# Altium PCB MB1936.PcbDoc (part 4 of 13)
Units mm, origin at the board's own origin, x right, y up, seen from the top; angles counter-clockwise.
Board outline 172 x 137 mm, 6 copper layers (Top Layer, Signal Layer 1, Signal Layer 2, Signal Layer 3, Signal Layer 4, Bottom Layer), stack 1.549 mm thick; 859 components, 672 nets, 3477 pads, 2222 vias.
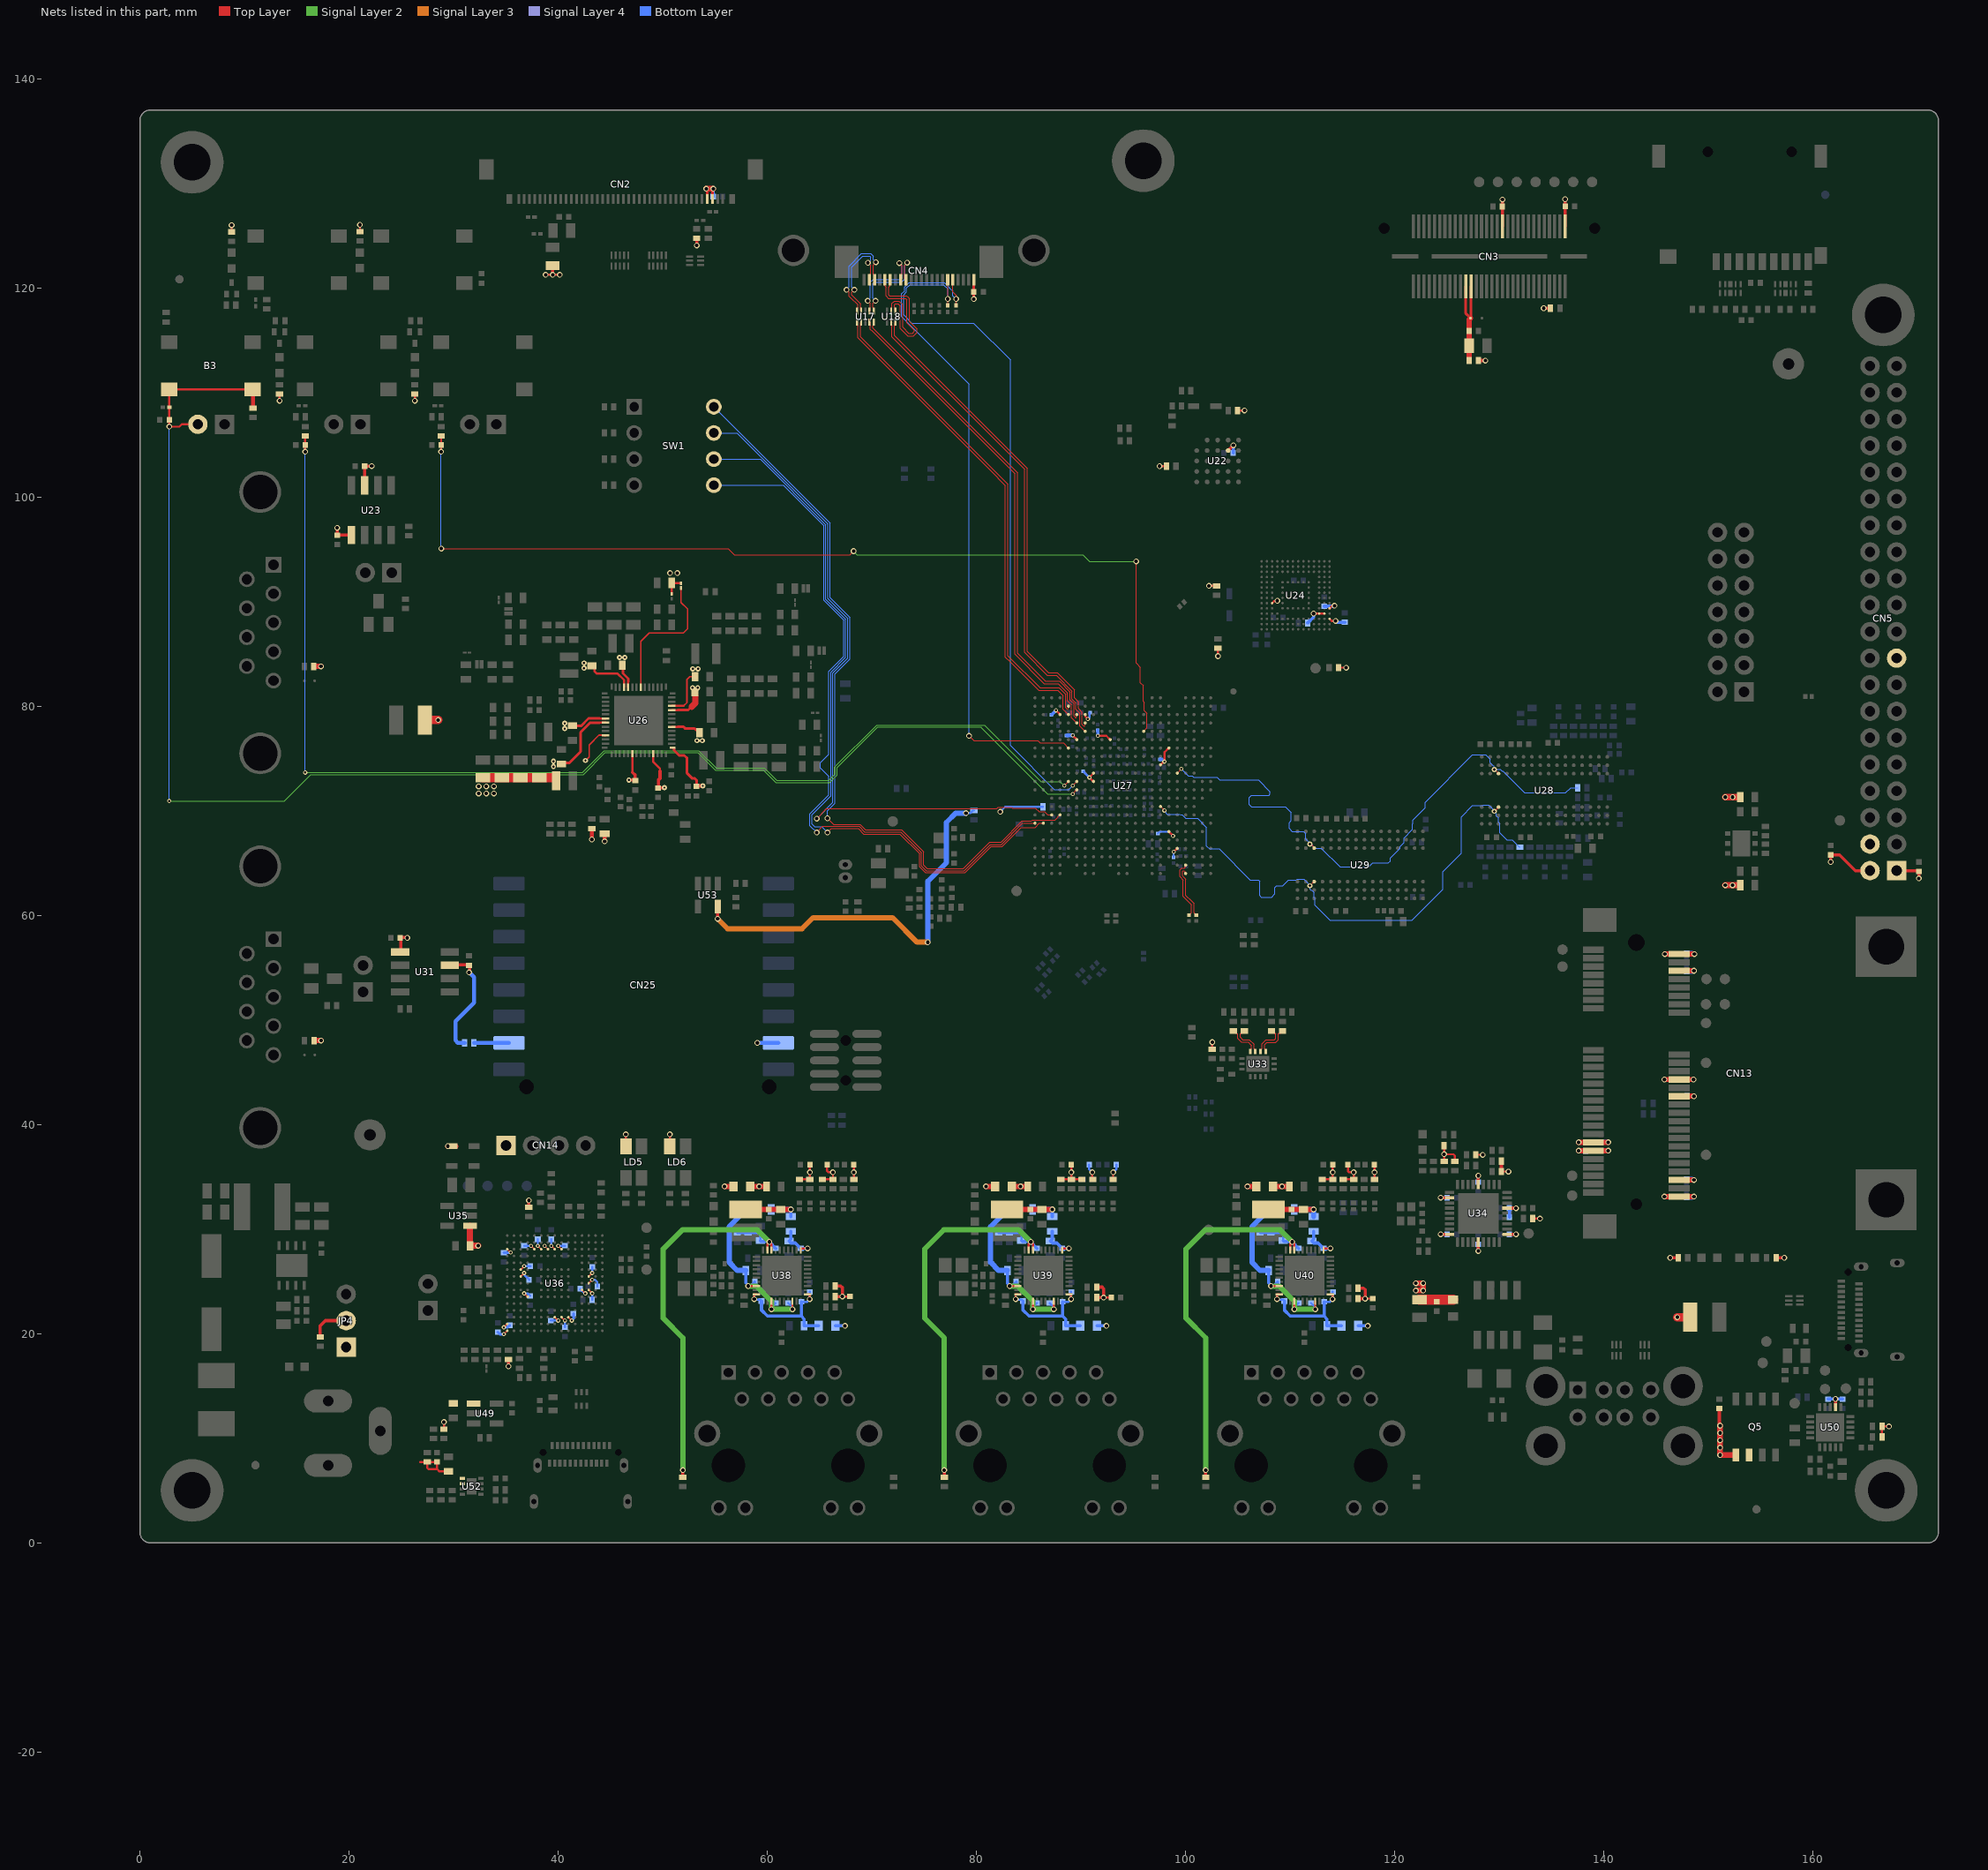
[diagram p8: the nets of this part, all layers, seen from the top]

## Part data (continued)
R93 R182 R183 R184 R188 R189 R190 R289: library part MCD-00052, "Resistor,0R,0402,5%,1/16W", Manufacturer=YAGEO, Manufacturer_Part_Number=RC0402JR-070RL, Package=0402
R94 R135 R136 R137 R138 R139 R140 R141 R142 R143 R144 R145 R146 R147 R148 R149 R150 R151 R152 R161 R162 R163 R164 R165 R166 R167 R168 R169 R173 R174 R175 R176 R177 R178 R179 R180 R185 R186 R187 R196 R197 R198 R247: library part MCD-02978, "Resistor, 22R, 0201, +/-1%, 1/20W", Manufacturer=YAGEO, Manufacturer_Part_Number=RC0201FR-0722RL, Package=0201
R95 R97 R98 R99 R100 R102 R105 R217 R218 R227 R229 R239: library part MCD-00059, "Resistor, 100K, 0402, +/-1%, 1/16W", Manufacturer=YAGEO, Manufacturer_Part_Number=RC0402FR-07100KL, Package=0402
R108 R109 R110 R111 R112 R113 R114 R115 R116 R117 R118 R119 R120 R121 R122 R123 R124 R292 R293 R294 R295 R296 R297 R298 R299 R300 R301 R302 R303 R304 R305 R306 R307: library part MCD-00065, "Resistor,4K7,0402,1%,1/16W", Alternate_Manufacturer=YAGEO, Alternate_Manufacturer_Part_Number=RT0402FRE074K7L, Manufacturer_Part_Number=RC0402FR-074K7L, Package=R0402
R130 R132: library part MCD-00062, "Resistor, 330R, 0402, +/-1%, 1/16W", Manufacturer=YAGEO, Manufacturer_Part_Number=RC0402FR-07330RL, Package=0402
R131 R133: library part MCD-02665, "Resistor, 1K, 0402, +/-0.1%, 1/16W, +/-25ppm/°C", Manufacturer=YAGEO, Manufacturer_Part_Number=RT0402BRD071KL, Package=0402
R134 R153 R207 R209: library part MCD-00455, "Resistor, 33R, 0402, +/-1%, 1/16W", Manufacturer=YAGEO, Manufacturer_Part_Number=RC0402FR-0733RL, Package=0402
R158 R159 R160 R315 R317 R319 R320 R321 R322: library part MCD-00065, "Resistor,4K7,0402,1%,1/16W", Alternate_Manufacturer=YAGEO, Alternate_Manufacturer_Part_Number=RT0402FRE074K7L, Manufacturer_Part_Number=RC0402FR-074K7L, Package=0402
R170: library part MCD-00187, "Resistor, 12K, 0402, +/-1%, 1/16W", Manufacturer=YAGEO, Manufacturer_Part_Number=RC0402FR-0712KL, Package=0402
R191 R192 R193 R195 R202 R203 R260 R261 R314 R316 R318: library part MCD-00068, "Resistor,1K5,0402,1%,1/16W", Manufacturer=YAGEO, Manufacturer_Part_Number=RC0402FR-071K5L, Package=0402
R194: library part MCD-00185, "Resistor, 3K, 0402, +/-1%, 1/16W", Manufacturer=YAGEO, Manufacturer_Part_Number=RC0402FR-073KL, Package=0402
R199 R200 R201: library part MCD-00183, "Resistor,2K49,0402,1%,1/16W", Manufacturer=YAGEO, Manufacturer_Part_Number=RC0402FR-072K49L, Package=0402
R204: library part MCD-00421, "Resistor,20K,0402,1%,1/16W", Alternate_Manufacturer=N/A, Manufacturer=YAGEO, Manufacturer_Part_Number=RC0402FR-0720KL, Package=0402
R208: library part MCD-00367, "Resistor,110K,0402,1%,1/16W", Alternate_Manufacturer=N/A, Manufacturer=YAGEO, Manufacturer_Part_Number=RC0402FR-07110KL, Package=0402
R216 R221 R222: library part MCD-00333, "Resistor, 5K1, 0402, +/-1%, 1/16W", Manufacturer=YAGEO, Manufacturer_Part_Number=RC0402FR-075K1L, Package=0402
R219: library part MCD-02335, "Resistor, 140K, 0402, +/-1%, 1/16W", Manufacturer=YAGEO, Manufacturer_Part_Number=RC0402FR-07140KL, Package=0402
R225: library part MCD-02232, "Resistor, 22mR, 0603, +/-1%, 1/3W", Manufacturer=PANASONIC, Manufacturer_Part_Number=ERJ-3BWFR022V, Package=0603
R231: library part MCD-00435, "Resistor, 24K, 0402, +/-1%, 1/16W", Manufacturer=YAGEO, Manufacturer_Part_Number=RC0402FR-0724KL, Package=0402
R232 R327: library part MCD-02265, "Resistor,100K,0402,0.5%,1/16W", Manufacturer=YAGEO, Manufacturer_Part_Number=RC0402DR-07100KL, Package=0402
R233 R234 R235 R236 R237 R238: library part MCD-00064, "Resistor,510R,0402,1%,1/16W", Manufacturer=YAGEO, Manufacturer_Part_Number=RC0402FR-07510RL, Package=0402
R240: library part MCD-00381, "Resistor, 1K3, 0402, +/-1%, 1/16W", Manufacturer=YAGEO, Manufacturer_Part_Number=RC0402FR-071K3L, Package=0402
R241: library part MCD-00409, "Resistor, 1K8, 0402, +/-1%, 1/16W", Manufacturer=YAGEO, Manufacturer_Part_Number=RC0402FR-071K8L, Package=0402
R242: library part MCD-02455, "Resistor, 3K9, 0402, +/-1%, 1/16W, +/-100ppm/°C", Manufacturer=YAGEO, Manufacturer_Part_Number=RC0402FR-073K9L, Package=0402
R243: library part MCD-00483, "Resistor, 470K, 0402, +/-1%, 1/16W", Manufacturer=YAGEO, Manufacturer_Part_Number=RC0402FR-07470KL, Package=0402
R244: library part MCD-00495, "Resistor, 560K, 0402, +/-1%, 1/16W", Manufacturer=YAGEO, Manufacturer_Part_Number=RC0402FR-07560KL, Package=0402
R249: library part MCD-00056, "Resistor, 0R, 0603, +/-5%, 1/10W", Manufacturer=YAGEO, Manufacturer_Part_Number=RC0603JR-070RL, Package=0603
R250 R251 R274 R285 R287: library part MCD-00417, "Resistor, 200R, 0402, +/-1%, 1/16W", Manufacturer=YAGEO, Manufacturer_Part_Number=RC0402FR-07200RL, Package=0402
R253 R254 R255 R256 R257 R258 R259 R263 R264 R265 R266 R268 R271 R273 R275 R276 R277 R278 R279 R280 R281 R282 R283 R284: library part MCD-00054, "Resistor, 56R, 0402, +/-1%, 1/16W", Alternate_Manufacturer=N/A, Manufacturer=YAGEO, Manufacturer_Part_Number=RC0402FR-0756RL, Package=0402
R270: library part MCD-01819, "Resistor,100R,0402,0,5%,1/16W,±100ppm/°C", Alternate_Manufacturer=N/A, Manufacturer=YAGEO, Manufacturer_Part_Number=RC0402DR-07100RL, Package=0402
R308 R309 R310 R311 R312 R313: library part MCD-00056, "Resistor,0R,0603,5%,1/10W", Manufacturer=YAGEO, Manufacturer_Part_Number=RC0603JR-070RL, Package=0603
R325: library part MCD-00182, "Resistor, 1M, 0402, +/-1%, 1/16W", Manufacturer=YAGEO, Manufacturer_Part_Number=RC0402FR-071ML, Package=0402
SB1: library part MCD-00071, "Solder Bridge ON", Manufacturer=YAGEO, Manufacturer_Part_Number=RC0603JR-070RL, Package=SB0603
SB2 SB3: library part MCD-01618, "Solder Bridge 0402 ON", Manufacturer=YAGEO, Manufacturer_Part_Number=RC0402JR-070RL, Package=SB0402
SW1: library part MCD-02256, "Quad SPST switch, TH, 2.54mm pitch, height 7.5mm", Alternate_Manufacturer="TE Connectivity", Alternate_Manufacturer_Part_Number=5435640-2, Manufacturer=GRAYHILL, Package="DIP8 2.54mm pitch"
TP1 TP2 TP3 TP4 TP5 TP6 TP7 TP34 TP36 TP37 TP38 TP39: library part MCD-00074, "Test Point 1mm", Manufacturer=N/A, Manufacturer_Part_Number=n/a
TP8 TP22: library part MCD-00713, "Vero Technologies 1.02mm Black Terminal Post", Manufacturer=VERO, Manufacturer_Part_Number=20-2137
TP9 TP11 TP12 TP13 TP14 TP15 TP16 TP17 TP18 TP19 TP20 TP21 TP23 TP24 TP25 TP26 TP27 TP28 TP29 TP30 TP31 TP32 TP35: library part MCD-00074, "Test Point 1mm", Manufacturer=n/a
TP10: library part MCD-00631, "Test Point 0.6mm", Manufacturer=N/A
TP33: library part MCD-00074, "Test Point 1mm", Manufacturer=N/A
U1 U2 U3 U4 U10 U11 U12 U13 U14 U15 U16 U19 U20 U21: library part MCD-00170, "ESD protection 6V1", Manufacturer=STMICROELECTRONICS, Manufacturer_HQ_COO=EU, Manufacturer_Part_Number=ESDALC6V1-1U2
U5 U6 U17: library part MCD-03059, "ESD protection & Common Filter High Speed serial Interfaces , 0.4 pitch", Manufacturer=STMICROELECTRONICS, Package=uQFN-10L
U7 U18 U42 U45 U46: library part MCD-03060, "ESD protection & Common Filter High Speed serial Interfaces , 0.4 pitch", Manufacturer=STMICROELECTRONICS, Package=uQFN-6
U8 U9: library part MCD-00667, "4-line ESD protection for high speed lines", Manufacturer=STMICROELECTRONICS, Manufacturer_HQ_COO=EU, Package=uQFN-10L
U22: library part MCD-00114, "Memory,Serial-NOR,512Mb,3V", Manufacturer=MACRONIX
U23 U31: library part MCD-00129, "High-Speed CAN Flexible Data Rate Transceiver", Manufacturer=MICROCHIP, Manufacturer_Part_Number=MCP2562FDT-H/SN
U24: library part MCD-02799, "Memory, eMMC, 4GB, 15nm ,WFBGA , 153 pins", Manufacturer=KIOXIA, Manufacturer_Part_Number=THGBMTG5D1LBAIL, Package=WFBGA153
U25 U32: library part MCD-00143, "Automotive dual-line Transil. ESD CAN", Manufacturer=STMICROELECTRONICS, Manufacturer_HQ_COO=EU, Manufacturer_Part_Number=ESDCAN24-2BLY
U26: library part MCD-03000, Manufacturer=STMICROELECTRONICS, Manufacturer_Part_Number=STPMIC25A, Package=VQFN
U27: library part MCD-02000, "MPU, ARM Cortex-A35 + M33 32-bit MPU, 808KB RAM, With Crypto", Manufacturer=STMICROELECTRONICS, Manufacturer_HQ_COO=EU, Package=LFBGA-436
U28 U29: library part MCD-03523, "Memory, DDR4 SDRAM, 1V2, 16Gbit, FBGA96", Manufacturer=MICRON, Package=FBGA-96
U30: library part MCD-00581, "LDO Linear Voltage Regulator IC Positive Adjustable 1 Output Adjustable 1.3A 6-DFN (3x3)", Manufacturer=STMICROELECTRONICS, Manufacturer_HQ_COO=EU, Package="DFN6 (3x3)"
U33: library part MCD-02349, "Crystal-less Two Output PCIe Gen1/2/3 Clock Generator 100Mhz , 2.25V to 3.6V, 100ppm", Manufacturer=MICROCHIP, Package="14 QFN"
U34: library part MCD-00145, "USB HUB 2,0 Controller", Manufacturer=MICROCHIP
U35: library part MCD-02514, "LDO, 3.3V, 300mA, High input voltage: 2.5V to 28V, SOT23-5L", Manufacturer=STMICROELECTRONICS, Package=SOT23-5L
U36: library part MCD-02706, "MCU, Arm Cortex-M7 32-bit MCU, 512KB Flash, 276KB RAM, With Crypto", Manufacturer=STMICROELECTRONICS, Manufacturer_Part_Number=STM32F723IEK6, Package=BGA176
U37: library part MCD-02219, "3 A DC step-down switching regulator", Manufacturer=STMICROELECTRONICS, Manufacturer_HQ_COO=EU, Package=VFQFPN
U38 U39 U40: library part MCD-01130, "10/100/1000M GIGABIT Ethernet Transceiver, QFN40 , SMPS version", Manufacturer=REALTEK
U41: library part MCD-00123, "IC,Dual-Channel-Power-Switch,500mA,100mR,SO8", Manufacturer=STMICROELECTRONICS, Manufacturer_HQ_COO=EU
U43 U48: library part MCD-01207, "High power Transient voltage suppressor:25V/35A EOS and ESD transients protection.", Manufacturer=STMICROELECTRONICS, Manufacturer_HQ_COO=EU, Manufacturer_Part_Number=ESDA25P35-1U1M, Package=QFN1610
U44 U51: library part MCD-01026, "High power transient voltage suppressor", Manufacturer=STMICROELECTRONICS, Manufacturer_HQ_COO=EU, Manufacturer_Part_Number=ESDA7P120-1U1M, Package=QFN1610
U47: library part MCD-00649, "Common mode filter with ESD protection for USB 2.0 interface", Manufacturer=STMICROELECTRONICS, Manufacturer_HQ_COO=EU, Manufacturer_Part_Number=ECMF02-2AMX6
U49: library part MCD-00159, "500mA, Enhanced single channel power switches with active high enable pin", Alternate_Manufacturer="TEXAS INSTRUMENTS", Alternate_Manufacturer_Part_Number=TPS2051C, Manufacturer=STMICROELECTRONICS, Manufacturer_HQ_COO=EU
U50: library part MCD-02130, "USB Type-C Port Protection for USB DRP Power Delivery, PPS compliant", Manufacturer=STMICROELECTRONICS, Manufacturer_HQ_COO=EU, Package=QFN-20L
U52: library part MCD-02532, "IC, eFuse with Fast Overvoltage Protection 2.7V to 18V 4A 34mOhm 8-Pin WSON", Manufacturer="TEXAS INSTRUMENTS", Package=WSON8
U53: library part MCD-02043, "Single,  rail to rail input/ouput 880Khz operational amplifiers", Manufacturer=STMICROELECTRONICS, Manufacturer_HQ_COO=EU, Package=SOT23-5
X1: library part MCD-01479, "Crystal, 32.768kHz, 6pF, +/-20ppm, 80K, 2.05x1.2mm", Manufacturer=NDK, Manufacturer_Part_Number=NX2012SA-32.768KHZ-EXS00A-MU00527, Package=2.05x1.2mm
X2: library part MCD-02343, "Oscillator, SPXO, 40Mhz, +/-50ppm, 1.8V, square wave, 1.6x1.2mm", Alternate_Manufacturer=N/A, Manufacturer=NDK, Manufacturer_Part_Number="NZ1612SH 40MHZ END5951A", Package=1.6x1.2mm
X3 X7: library part MCD-01036, "Crystal, 24MHz, 6pF, +/-20ppm, 80R, 2x1.6mm", Manufacturer=NDK, Manufacturer_Part_Number=NX2016SA-24MHZ-EXS00A-CS10820, Package=2x1.6mm
X4 X5 X6: library part MCD-01463, "Crystal 25Mhz, 10pF, -+50PPM, SMD", Manufacturer=NDK, Manufacturer_Part_Number=NX3225GA-25MHZ-EXS00A-CG06750, Package=3.2x2.5mm

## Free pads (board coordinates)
  round 3 hole 2.2 paste-2539.97 mask+0.05: 1(62.5,123.578) 1(85.5,123.578)
  round 6 hole 3.5: 1(166.725,117.4) 7(95.954,132.163)
  round 6 hole 3.5 mask+0.05: 5(5,5) 5(5,132) 5(167,5)

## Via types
v1: diameter 0.55, hole 0.35, Top Layer to Bottom Layer, 1661 vias
v2: diameter 0.4, hole 0.2, Top Layer to Bottom Layer, tented both sides, 253 vias
v3: diameter 0.5, hole 0.2, Top Layer to Bottom Layer, 157 vias
v4: diameter 0.5, hole 0.25, Top Layer to Bottom Layer, 145 vias
v5: diameter 0.4, hole 0.2, Top Layer to Bottom Layer, 6 vias

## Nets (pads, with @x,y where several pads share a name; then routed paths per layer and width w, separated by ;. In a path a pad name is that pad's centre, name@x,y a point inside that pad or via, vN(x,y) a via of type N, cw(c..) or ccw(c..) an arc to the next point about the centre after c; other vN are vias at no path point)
1V0_AVDD_RGMII1: C301.2 C305.2 C320.2 C321.2 R309.1 U39.3 U39.8 U39.38 | length 20.5
  Top Layer w0.2: v1(83.175,24.55) U39.38@83.95,24.55 ; v1(85.4,22.325) U39.3@85.4,23.1 ; v1(87.4,22.325) U39.8@87.4,23.1
  Signal Layer 2 w0.5: v1(83.175,24.55) 83.95,24.55 85.4,23.1 v1(85.4,22.325) v1(87.4,22.325)
  Bottom Layer w0.2: v1(85.4,22.325) 85.4,22.525 C321.2@85.8,22.925 ; C320.2@87,22.925 87.4,22.525 v1(87.4,22.325)
  Bottom Layer w0.3: C301.2@82.931,26.044 C301.2@82.95,26.025 82.95,24.843 83.175,24.618 v1(83.175,24.55) 83.223,24.598 83.448,24.598 83.67,24.82 83.695,24.82 83.8,24.925 C305.2@83.8,24.95
  Bottom Layer w0.5: C301.2@82.931,26.044 82.125,26.044 81.35,26.819 81.35,30.225 83,31.875 R309.1@83.975,31.875
1V0_AVDD_RGMII2: C302.2 C306.2 C322.2 C323.2 R310.1 U38.3 U38.8 U38.38 | length 20.5
  Top Layer w0.2: v1(58.175,24.55) U38.38@58.95,24.55 ; v1(60.4,22.325) U38.3@60.4,23.1 ; v1(62.4,22.325) U38.8@62.4,23.1
  Signal Layer 2 w0.5: v1(58.175,24.55) 58.95,24.55 60.4,23.1 v1(60.4,22.325) v1(62.4,22.325)
  Bottom Layer w0.2: v1(60.4,22.325) 60.4,22.525 C323.2@60.8,22.925 ; C322.2@62,22.925 62.4,22.525 v1(62.4,22.325)
  Bottom Layer w0.3: C302.2@57.931,26.044 C302.2@57.95,26.025 57.95,24.843 58.175,24.618 v1(58.175,24.55) 58.223,24.598 58.448,24.598 58.67,24.82 58.695,24.82 58.8,24.925 C306.2@58.8,24.95
  Bottom Layer w0.5: C302.2@57.931,26.044 57.125,26.044 56.35,26.819 56.35,30.225 58,31.875 R310.1@58.975,31.875
1V0_AVDD_RGMII3: C300.2 C304.2 C318.2 C319.2 R308.1 U40.3 U40.8 U40.38 | length 20.5
  Top Layer w0.2: v1(108.175,24.55) U40.38@108.95,24.55 ; v1(110.4,22.325) U40.3@110.4,23.1 ; v1(112.4,22.325) U40.8@112.4,23.1
  Signal Layer 2 w0.5: v1(108.175,24.55) 108.95,24.55 110.4,23.1 v1(110.4,22.325) v1(112.4,22.325)
  Bottom Layer w0.2: v1(110.4,22.325) 110.4,22.525 C319.2@110.8,22.925 ; C318.2@112,22.925 112.4,22.525 v1(112.4,22.325)
  Bottom Layer w0.3: C300.2@107.931,26.044 C300.2@107.95,26.025 107.95,24.843 108.175,24.618 v1(108.175,24.55) 108.223,24.598 108.448,24.598 108.67,24.82 108.695,24.82 108.8,24.925 C304.2@108.8,24.95
  Bottom Layer w0.5: C300.2@107.931,26.044 107.125,26.044 106.35,26.819 106.35,30.225 108,31.875 R308.1@108.975,31.875
1V0_DVDD_RGMII1: C287.2 C293.2 R312.1 U39.21 | length 3.9
  Top Layer w0.2: U39.21@88.2,28 88.2,28.15 v1(88.85,28.15)
  Bottom Layer w0.3: R312.1@87.25,29.8 87.25,29.025 C287.2@87.075,28.85 87.257,28.668 87.682,28.668 88.02,28.33 88.02,28.305 88.175,28.15 v1(88.85,28.15)
1V0_DVDD_RGMII2: C288.2 C295.2 R313.1 U38.21 | length 3.9
  Top Layer w0.2: U38.21@63.2,28 63.2,28.15 v1(63.85,28.15)
  Bottom Layer w0.3: R313.1@62.25,29.8 62.25,29.025 C288.2@62.075,28.85 62.257,28.668 62.682,28.668 63.02,28.33 63.02,28.305 63.175,28.15 v1(63.85,28.15)
1V0_DVDD_RGMII3: C286.2 C291.2 R311.1 U40.21 | length 3.9
  Top Layer w0.2: U40.21@113.2,28 113.2,28.15 v1(113.85,28.15)
  Bottom Layer w0.3: R311.1@112.25,29.8 112.25,29.025 C286.2@112.075,28.85 112.257,28.668 112.682,28.668 113.02,28.33 113.02,28.305 113.175,28.15 v1(113.85,28.15)
1V0_RGMII1: C121.2 C124.2 LE2.2 R309.2 R312.2 | length 6.9
  Top Layer w0.5: LE2.2@82.925,31.875 C124.2@85.15,31.875 C121.2@86.275,31.875 v1(87.25,31.875)
  Bottom Layer w0.3: R312.2@87.25,31.2 v1(87.25,31.875)
  Bottom Layer w0.5: R309.2@85.375,31.875 v1(87.25,31.875)
1V0_RGMII2: C120.2 C123.2 LE1.2 R310.2 R313.2 | length 6.9
  Top Layer w0.5: LE1.2@57.925,31.875 C123.2@60.15,31.875 C120.2@61.275,31.875 v1(62.25,31.875)
  Bottom Layer w0.3: R313.2@62.25,31.2 v1(62.25,31.875)
  Bottom Layer w0.5: R310.2@60.375,31.875 v1(62.25,31.875)
1V0_RGMII3: C122.2 C125.2 LE3.2 R308.2 R311.2 | length 6.9
  Top Layer w0.5: LE3.2@107.925,31.875 C125.2@110.15,31.875 C122.2@111.275,31.875 v1(112.25,31.875)
  Bottom Layer w0.5: R308.2@110.375,31.875 v1(112.25,31.875) R311.2@112.25,31.2
1V5_PCIE: C266.1 C267.1 C272.1 CN13.6 CN13.28 CN13.48 R69.2 | length 7.9
  Top Layer w0.5: CN13.48@147.2,34.7 v1(148.612,34.7) ; CN13.28@147.2,42.7 v1(148.612,42.7) ; CN13.6@147.2,54.7 v1(148.612,54.7)
  Top Layer w0.6: v1(151.609,62.875) v1(152.309,62.875) R69.2@153.05,62.875
  Bottom Layer w0.3: C272.1@147.9,34.85 148.462,34.85 v1(148.612,34.7) ; C266.1@147.9,54.55 148.462,54.55 v1(148.612,54.7) ; C267.1@147.95,42.8 148.512,42.8 v1(148.612,42.7)
1V8: C1.2 C178.2 C179.2 C190.2 C191.2 C193.2 C194.2 C206.2 C212.2 C246.2 C253.2 CN3.60 LNK1.2 LNK3.2 R35.2 R37.2 R44.2 R49.2 R248.2 R267.2 R269.1 U24.C6 U24.M4 U24.N4 U24.P3 U24.P5 U27.C4 U27.C7 U27.F6 U27.F10 U27.G17 U27.J16 U27.K8 U27.L8 U27.U17 U27.W18 U53.5 | length 69
  Top Layer w0.2: LNK3.2@50.855,90.695 LNK3.2@50.855,90.725 R35.2@50.855,91.777 50.882,91.75 LNK1.2@51.75,91.75 ; v2(87.6,79.6) U27.C4@88,79.2 v2(87.6,79.6) ; v2(89.2,77.2) U27.F6@89.6,76.8 ; U27.C7@90.4,79.2 90.415,79.185 90.415,79.02 v2(90.66,78.775) ; U27.L8@91.2,72.8 91.175,72.8 v2(90.8,73.175) 91.2,73.575 U27.K8@91.2,73.6 ; v2(91.624,77.173) 92.413,77.173 92.786,76.8 U27.F10@92.8,76.8 ; U27.J16@97.6,74.4 97.627,74.4 97.927,74.7 v2(97.975,74.7) 98,74.725 98,75.6 U27.G17@98.4,76 ; U27.U17@98.4,68 v2(98.8,67.6) ; v2(98.868,66.067) U27.W18@99.2,66.4 ; v1(102.23,91.5) R37.2@102.975,91.5 ; v1(103.1,84.783) R44.2@103.1,85.528 ; U24.C6@108.275,89.85 108.452,90.027 108.727,90.027 v1(108.775,90.075) ; v1(112.25,88.85) U24.M4@112.775,88.85 U24.N4@113.275,88.85 ; U24.P3@113.775,88.35 113.975,88.15 v1(114.35,88.15) ; U24.P5@113.775,89.35 114.005,89.58 114.23,89.58 v1(114.25,89.6) ; R49.2@114.625,83.685 v1(115.35,83.685)
  Top Layer w0.3: v1@55.263,59.687 U53.5@55.263,60.838 ; CN3.60@136.3,125.87 C1.2@136.3,127.796 v1(136.3,128.471)
  Signal Layer 3 w0.5: v1(55.25,59.675) 56.2,58.725 63.325,58.725 64.375,59.775 71.975,59.775 74.325,57.425 v1(75.35,57.425)
  Signal Layer 4 w0.3: v2@97.956,74.719 v2(97.975,74.7)
  Bottom Layer w0.09: v2@97.87,74.805 v2(97.975,74.7)
  Bottom Layer w0.17: C246.2@97.35,67.825 97.415,67.89 97.44,67.89 97.56,68.01 98.39,68.01 v2(98.8,67.6)
  Bottom Layer w0.2: v1(79,69.775) 79.018,69.793 79.448,69.793 79.668,70.013 R269.1@79.763,70.013 ; v1(82.275,69.9) 82.75,70.375 R267.2@86.35,70.375 ; C212.2@90.25,73.775 90.25,73.725 v2(90.8,73.175) ; v2(90.66,78.775) 90.66,78.79 90.825,78.955 C190.2@90.825,79.375 ; C253.2@98.85,65.55 98.85,66.05 v2(98.868,66.067)
  Bottom Layer w0.3: C191.2@87.175,79.175 v2(87.6,79.6) ; C193.2@91.6,77.7 91.6,77.224 91.624,77.2 v2(91.624,77.173) ; C206.2@97.555,74.91 97.765,74.91 v2@97.87,74.805 ; R248.2@111.675,87.95 112.241,88.516 112.241,88.841 v1(112.25,88.85) ; C178.2@113.275,89.55 114.132,89.55 114.182,89.6 v1(114.25,89.6) ; v1(114.35,88.15) 114.418,88.15 114.543,88.025 C179.2@115.225,88.025
  Bottom Layer w0.4: C194.2@88.675,77.2 v2(89.2,77.2)
  Bottom Layer w0.5: v1(75.35,57.425) 75.35,63.25 77.125,65.025 77.125,68.875 78.025,69.775 v1(79,69.775)
  other v1: 50.7,92.725 51.4,92.725
1V8_FB: LNK1.1 U26.35 | length 13.5
  Top Layer w0.15: U26.35@47.9,81.797 47.9,86.2 48.7,87 51.975,87 52.375,87.4 52.375,89.3 51.75,89.925 LNK1.1@51.75,91.3
3V3: C2.2 C7.2 C15.2 C57.2 C58.2 C59.2 C60.2 C69.1 C96.2 C174.2 C175.2 C265.1 C268.1 C269.2 C273.2 C274.1 C275.2 C276.2 C277.2 C283.2 C284.2 C285.2 C334.1 C335.1 CN2.3 CN2.4 CN3.36 CN4.22 CN5.1 CN5.17 CN13.2 CN13.24 CN13.39 CN13.41 CN13.52 CN25.7 L7.2 L9.2 L10.2 L11.2 L13.2 L14.2 L15.2 R1.1 R3.1 R4.1 R9.1 R19.2 R20.2 R23.2 R33.2 R50.1 R55.1 R57.1 R86.1 R92.1 R97.2 R99.2 R100.2 R103.2 R104.1 R106.2 R157.2 R171.2 R172.1 R224.2 R228.2 U22.B4 U23.5 U26.53 U31.5 U34.5 U34.10 U34.15 U34.23 U34.29 U34.36 U50.2 | length 82.3
  Top Layer w0.15: v3(42.61,74.804) 42.962,75.156 42.962,76.292 43.897,77.227 U26.53@44.53,77.227 ; U26.53@44.32,77.196 44.619,77.196 U26.53@44.65,77.227
  Top Layer w0.2: R4.1@8.773,125.35 v1(8.773,126) ; v1(13.363,109.2) R19.2@13.363,109.85 ; R3.1@21.047,125.375 v1(21.047,126.025) ; v1(26.287,109.2) R20.2@26.287,109.85 ; v1(97.509,102.95) R33.2@98.184,102.95 ; R92.1@102.55,47.19 v1(102.55,47.865) ; R23.2@104.966,108.275 v1(105.641,108.275) ; R103.2@124.725,36.475 v1(124.725,37.15) ; R97.2@124.725,37.975 v1(124.725,37.15) ; R104.1@125.75,36.475 125.75,37.025 125.625,37.15 v1(124.725,37.15) ; R99.2@127.75,37.105 v1(128.425,37.105) ; R106.2@130.2,35.5 v1(130.875,35.5) ; R157.2@133.211,31 v1(133.886,31) ; R228.2@166.595,10.125 R224.2@166.595,11.125 v1(167.27,11.125)
  Top Layer w0.25: v1(54.163,129.475) 54.163,129.394 54.25,129.306 CN2.4@54.25,128.5 ; CN2.3@54.75,128.5 v1@54.75,129.388 ; v1(79.75,118.925) C7.2@79.75,119.6 CN4.22@79.75,120.75
  Top Layer w0.3: v1(18.869,97.046) 18.869,96.371 U23.5@20.224,96.371 ; U31.5@24.945,56.545 24.945,57.9 v1@25.62,57.9 ; v1(53.25,124.051) R1.1@53.25,124.745 ; v1@54.75,129.388 v1(54.838,129.475) ; U22.B4@104.066,104.441 v1(104.566,104.941) ; v1(124.4,29.5) U34.36@125.25,29.5 ; v1(124.4,33) U34.29@125.25,33 ; v1(128,27.9) U34.5@128,28.75 ; U34.23@128,34.25 v1(128,35.1) ; R106.2@130.2,35.5 R100.2@130.2,36.5 ; CN3.36@130.3,125.87 C2.2@130.3,127.775 v1(130.3,128.45) ; U34.10@130.75,29.5 v1(131.6,29.5) ; U34.15@130.75,32 v1(131.6,32) ; v1(134.25,118.05) R9.1@134.9,118.05 ; v1(146.35,27.25) R171.2@147.125,27.25 ; R172.1@156.475,27.25 v1(157.25,27.25) ; U50.2@162.15,12.975 v1(162.15,13.75) ; CN5.1@167.995,64.27 170.055,64.27 C69.1@170.125,64.2 v1(170.125,63.525)
  Top Layer w0.4: v1(43.225,67.25) R57.1@43.225,68.302
  Top Layer w0.5: R50.1@16.647,83.8 v1(17.322,83.8) ; R86.1@16.65,48.025 v1(17.325,48.025) ; v1(55.915,34.07) L9.2@56.77,34.07 ; v1(80.915,34.07) L10.2@81.77,34.07 ; v1(105.915,34.07) L11.2@106.77,34.07 ; v1(137.587,37.5) CN13.41@139,37.5 v1(140.412,37.5) ; v1(137.587,38.3) CN13.39@139,38.3 v1(140.412,38.3) ; v1(145.787,33.1) CN13.52@147.2,33.1 v1(148.612,33.1) ; v1(145.787,44.3) CN13.24@147.2,44.3 v1(148.57,44.3) ; v1(145.83,56.3) CN13.2@147.2,56.3 v1(148.655,56.3)
  Top Layer w0.55: v1(54.163,129.475) v1(54.838,129.475)
  Top Layer w0.6: v1(151.614,71.3) v1(152.314,71.3) R55.1@153.055,71.3
  Top Layer w0.9: C57.2@32.8,73.15 C58.2@34.6,73.15 C59.2@36.4,73.15 C60.2@38.2,73.15 39.575,73.15 L7.2@39.6,73.125
  Bottom Layer w0.3: C174.2@54.825,128.725 54.838,128.737 v1(54.838,129.475) ; L15.2@66.52,20.75 v1(67.425,20.75) ; L14.2@91.52,20.75 v1(92.425,20.75) ; C175.2@104.566,104.216 v1(104.566,104.941) ; L13.2@116.52,20.75 v1(117.425,20.75) ; v1(124.4,29.5) C284.2@125.025,29.5 ; v1(124.4,33) C275.2@125.025,33 ; v1(128,27.9) C285.2@128,28.525 ; C273.2@128,34.475 v1(128,35.1) ; C283.2@130.975,29.5 v1(131.6,29.5) ; C277.2@130.975,31.125 C276.2@130.975,32 v1(131.6,32) ; v1(137.587,37.5) 137.688,37.4 C269.2@138.25,37.4 ; C268.1@139.75,38.4 140.312,38.4 v1(140.412,38.3) ; C274.1@147.9,32.95 148.462,32.95 v1(148.612,33.1) ; C265.1@147.9,56.45 148.462,56.45 v1@148.612,56.3 ; C335.1@161.45,13.75 v1(162.15,13.75) C334.1@162.85,13.75
  Bottom Layer w0.4: v1@59.045,47.8 CN25.7@61.055,47.8
  other v1: 59.04,47.805 25.565,57.845 32.4,71.65 33.125,71.65 33.85,71.65 32.4,72.325 33.125,72.325 33.85,72.325
3V3_AVDD_RGMII1: C308.2 C313.2 C316.2 C331.2 L14.1 U39.11 U39.40 | length 12.4
  Top Layer w0.2: v1(83.75,23.3) 83.75,23.75 U39.40@83.95,23.75 ; U39.11@88.85,23.75 89.05,23.75 v1(89.05,23.3)
  Bottom Layer w0.2: v1(83.75,23.3) 83.817,23.233 84.332,23.233 C313.2@84.445,23.12 ; C316.2@88.25,23.05 88.8,23.05 v1(89.05,23.3) C308.2@89.05,24
  Bottom Layer w0.3: C313.2@84.445,23.12 84.445,22.255 85.025,21.675 88.25,21.675 ; C316.2@88.25,23.05 88.25,21.675 ; L14.1@89.92,20.75 C331.2@88.525,20.75 88.525,21.4 88.25,21.675
3V3_AVDD_RGMII2: C309.2 C314.2 C317.2 C332.2 L15.1 U38.11 U38.40 | length 12.4
  Top Layer w0.2: v1(58.75,23.3) 58.75,23.75 U38.40@58.95,23.75 ; U38.11@63.85,23.75 64.05,23.75 v1(64.05,23.3)
  Bottom Layer w0.2: v1(58.75,23.3) 58.817,23.233 59.332,23.233 C314.2@59.445,23.12 ; C317.2@63.25,23.05 63.8,23.05 v1(64.05,23.3) C309.2@64.05,24
  Bottom Layer w0.3: C314.2@59.445,23.12 59.445,22.255 60.025,21.675 63.25,21.675 ; C317.2@63.25,23.05 63.25,21.675 ; L15.1@64.92,20.75 C332.2@63.525,20.75 63.525,21.4 63.25,21.675
3V3_AVDD_RGMII3: C307.2 C312.2 C315.2 C330.2 L13.1 U40.11 U40.40 | length 12.4
  Top Layer w0.2: v1(108.75,23.3) 108.75,23.75 U40.40@108.95,23.75 ; U40.11@113.85,23.75 114.05,23.75 v1(114.05,23.3)
  Bottom Layer w0.2: v1(108.75,23.3) 108.817,23.233 109.332,23.233 C312.2@109.445,23.12 ; C315.2@113.25,23.05 113.8,23.05 v1(114.05,23.3) C307.2@114.05,24
  Bottom Layer w0.3: C312.2@109.445,23.12 109.445,22.255 110.025,21.675 113.25,21.675 ; C315.2@113.25,23.05 113.25,21.675 ; L13.1@114.92,20.75 C330.2@113.525,20.75 113.525,21.4 113.25,21.675
3V3_DVDD_RGMII1: C105.2 C112.2 C142.2 C270.2 C271.2 C279.1 C294.2 L10.1 R108.2 R115.2 R116.2 R117.2 R118.2 R192.2 R202.2 R235.2 R316.2 R317.1 U39.28 U39.29 | length 51.4
  Top Layer w0.2: U39.29@85,28 85,28.575 v1(85.2,28.775) 85.4,28.575 U39.28@85.4,28 ; R115.2@88.075,34.75 R116.2@89.075,34.75 ; C105.2@89.075,36.17 v1(89.075,35.425) R116.2@89.075,34.75 ; R117.2@90.075,34.75 R116.2@89.075,34.75 ; v1(91.075,35.425) 91.075,34.8 R108.2@91.125,34.75 ; v1(92.17,23.45) C142.2@92.9,23.45 ; R118.2@93.075,34.75 v1(93.075,35.425)
  Top Layer w0.3: R235.2@76.925,6.275 v1(76.925,6.95) ; R202.2@91.495,23.45 v1(92.17,23.45) 92.17,24.308 92.028,24.45 R192.2@91.495,24.45 R192.2@91.495,24.413
  Top Layer w0.5: L10.1@83.37,34.07 v1(84.225,34.07) C112.2@84.92,34.07
  Signal Layer 2 w0.5: v1(76.925,6.95) 76.925,19.6 75.05,21.475 75.05,28.1 76.875,29.925 84.05,29.925 v1(85.2,28.775)
  Bottom Layer w0.2: R317.1@82.125,29.625 R316.2@83.15,29.625 84.13,29.625 84.325,29.43 C279.1@84.325,28.9 ; C271.2@90.775,36.15 90.775,35.725 v1(91.075,35.425) ; v1(93.075,35.425) 93.375,35.725 C270.2@93.375,36.15
  Bottom Layer w0.3: C279.1@84.325,28.9 84.402,28.823 85.152,28.823 v1(85.2,28.775) 85.2,28.75 C294.2@85.8,28.15
3V3_DVDD_RGMII2: C103.2 C104.2 C109.2 C111.2 C141.2 C280.1 C296.2 L9.1 R109.2 R110.2 R111.2 R112.2 R114.2 R191.2 R195.2 R233.2 R318.2 R319.1 U38.28 U38.29 | length 51.6
  Top Layer w0.2: U38.29@60,28 60,28.575 v1(60.2,28.775) 60.4,28.575 U38.28@60.4,28 ; R109.2@63.075,34.75 R110.2@64.075,34.75 v1(64.075,35.425) C103.2@64.075,36.17 ; R111.2@65.275,34.75 R112.2@66.275,34.75 v1(66.275,35.425) 65.842,35.425 65.725,35.542 C104.2@65.725,36.17 ; v1(67.17,23.55) C141.2@67.9,23.55 ; R114.2@68.275,34.75 v1(68.275,35.425) C109.2@68.275,36.15
  Top Layer w0.3: R233.2@51.925,6.275 v1(51.925,6.95) ; R195.2@66.495,23.55 v1(67.17,23.55) 67.17,24.408 67.028,24.55 R191.2@66.495,24.55 R191.2@66.495,24.513
  Top Layer w0.5: L9.1@58.37,34.07 v1(59.225,34.07) C111.2@59.92,34.07
  Signal Layer 2 w0.5: v1(51.925,6.95) 51.925,19.6 50.05,21.475 50.05,28.1 51.875,29.925 59.05,29.925 v1(60.2,28.775)
  Bottom Layer w0.2: R319.1@57.125,29.625 R318.2@58.15,29.625 59.13,29.625 59.325,29.43 C280.1@59.325,28.9
  Bottom Layer w0.3: C280.1@59.325,28.9 59.402,28.823 60.152,28.823 v1(60.2,28.775) 60.2,28.75 C296.2@60.8,28.15
3V3_DVDD_RGMII3: C106.2 C107.2 C108.2 C113.1 C144.2 C278.2 C292.2 L11.1 R119.2 R120.2 R121.2 R122.2 R124.2 R193.2 R203.2 R237.2 R314.2 R315.1 U40.28 U40.29 | length 51.6
  Top Layer w0.2: U40.29@110,28 110,28.575 v1(110.2,28.775) 110.4,28.575 U40.28@110.4,28 ; R119.2@113.075,34.75 R120.2@114.075,34.75 v1(114.075,35.425) C106.2@114.075,36.17 ; R121.2@115.075,34.75 R122.2@116.075,34.75 v1(116.075,35.425) 115.642,35.425 115.525,35.542 C107.2@115.525,36.17 ; v1(117.17,23.35) C144.2@117.9,23.35 ; R124.2@118.075,34.75 v1(118.075,35.425) C108.2@118.075,36.15
  Top Layer w0.3: R237.2@101.925,6.275 v1(101.925,6.95) ; R203.2@116.495,23.35 v1(117.17,23.35) 117.17,24.208 117.028,24.35 R193.2@116.495,24.35 R193.2@116.495,24.313
  Top Layer w0.5: L11.1@108.37,34.07 v1(109.225,34.07) C113.1@109.92,34.07
  Signal Layer 2 w0.5: v1(101.925,6.95) 101.925,19.6 100.05,21.475 100.05,28.1 101.875,29.925 109.05,29.925 v1(110.2,28.775)
  Bottom Layer w0.2: R315.1@107.125,29.625 R314.2@108.15,29.625 109.13,29.625 109.325,29.43 C278.2@109.325,28.9
  Bottom Layer w0.3: C278.2@109.325,28.9 109.402,28.823 110.152,28.823 v1(110.2,28.775) 110.2,28.75 C292.2@110.8,28.15
3V3_STLK: C129.2 C281.1 C282.1 C289.1 C290.1 C297.1 C298.1 C299.1 C303.1 C310.1 C311.1 C324.1 C325.1 C326.1 C327.1 C328.1 C329.1 C333.1 CN14.1 LD5.4 LD6.4 R156.2 R227.1 U35.1 U36.C1 U36.C5 U36.C6 U36.C7 U36.C8 U36.C9 U36.F3 U36.G3 U36.G13 U36.H13 U36.J12 U36.J13 U36.K4 U36.N8 U36.N9 U36.N10 U36.P1 U36.R1 | length 26.2
  Top Layer w0.15: v2(34.8,19.95) U36.R1@35.125,20.275 ; v2(34.8,20.6) U36.P1@35.125,20.925 ; U36.C1@35.125,28.075 v2(35.45,27.75) ; U36.G3@36.425,25.475 v2(36.75,25.8) ; U36.F3@36.425,26.125 v2(36.75,26.45) ; v2(36.75,23.85) U36.K4@37.075,23.525 ; v2(37.4,28.4) U36.C5@37.725,28.075 ; v2(38.05,28.4) U36.C6@38.375,28.075 ; v2(38.7,28.4) U36.C7@39.025,28.075 ; v2(39.35,28.4) U36.C8@39.675,28.075 ; U36.N8@39.675,21.575 v2(40,21.25) ; v2(40,28.4) U36.C9@40.325,28.075 ; U36.N9@40.325,21.575 v2(40.65,21.25) ; U36.N10@40.975,21.575 v2(41.3,21.25) ; U36.J12@42.275,24.175 v2(42.6,23.85) ; U36.J13@42.925,24.175 v2(43.25,23.85) ; U36.H13@42.925,24.825 v2(43.25,25.15) ; U36.G13@42.925,25.475 v2(43.25,25.8)
  Top Layer w0.2: R227.1@29.075,10.875 v1(29.075,11.55) ; LD5.4@46.475,37.9 v1(46.475,39.05) ; LD6.4@50.675,37.9 v1(50.675,39.05)
  Top Layer w0.3: R156.2@37.2,32.1 v1(37.2,32.745)
  Top Layer w0.6: U35.1@31.57,30.325 C129.2@31.57,28.4 v1(32.345,28.4)
  Bottom Layer w0.2: v2(36.75,23.85) 37.075,23.85 C324.1@37.325,23.6 ; v2(36.75,25.8) 36.788,25.762 36.788,25.587 37.045,25.33 37.07,25.33 37.225,25.175 C303.1@37.225,25.15 ; v2(36.75,26.45) C299.1@37.35,26.45 ; C289.1@36.75,28.4 v2(37.4,28.4) ; v2(38.05,28.4) C282.1@38.05,29.025 ; C327.1@39.3,21.25 v2(40,21.25) ; v2(39.35,28.4) C281.1@39.35,29.025 ; v2(40,28.4) C290.1@40.65,28.4 ; C333.1@40.65,20.625 v2(40.65,21.25) ; C311.1@42.1,24.275 42.1,24.25 42.255,24.095 42.28,24.095 42.487,23.888 42.562,23.888 v2(42.6,23.85) ; C325.1@43.25,23.225 v2(43.25,23.85) ; v2(43.25,25.15) 43.53,25.15 43.75,24.93 C310.1@43.75,24.5 ; v2(43.25,25.8) C298.1@43.25,26.375
  Bottom Layer w0.25: C329.1@34.225,20.15 34.425,19.95 v2(34.8,19.95) ; v2(34.8,20.6) 35.175,20.6 C328.1@35.375,20.8 ; C297.1@34.8,27.75 v2(35.45,27.75) ; v2(41.3,21.25) 41.455,21.405 C326.1@41.455,21.9
5V: CN25.10 R289.2 | length 3.4
  Bottom Layer w0.4: R289.2@31.95,47.813 31.962,47.8 CN25.10@35.295,47.8
5V_STI: C9.2 C10.2 CN3.21 CN3.23 R18.2 SB1.2 | length 10.4
  Top Layer w0.25: CN3.21@126.8,120.13 126.8,117.55 SB1.2@127.25,117.1 127.3,117.15 CN3.23@127.3,120.13
  Top Layer w0.5: R18.2@127.123,113.05 C10.2@127.123,114.475 C9.2@127.123,115.875 127.123,116.973 SB1.2@127.25,117.1
5V_STLK: C165.2 C169.2 C176.1 JP4.1 R230.1 U49.1 U52.5 U52.6 | length 5
  Top Layer w0.2: 26.8,7.725 R230.1@27.475,7.725 ; C169.2@29.52,6.825 28.65,6.825 28.425,7.05 ; R230.1@27.475,7.725 27.475,7.175 27.6,7.05 28.425,7.05 ; R230.1@27.475,7.725 C176.1@28.425,7.725 28.425,7.05
5V_VIN: C14.1 C29.2 C30.2 C32.2 C38.2 C42.1 C45.2 C46.2 C56.2 C62.2 C64.2 C67.2 C68.2 C100.1 C143.2 C146.2 C147.1 C162.2 CN5.2 CN5.4 D2.1 JP4.2 L12.1 Q5.5 Q5.6 R5.2 R18.1 R56.1 R210.2 R216.2 R289.1 U23.3 U26.6 U26.11 U26.15 U26.20 U26.24 U26.25 U26.38 U26.39 U26.49 U26.50 U31.3 | length 82.1
  Top Layer w0.15: 52,80.027 52.325,80.352 52.325,82.558 52.588,82.821 53.019,82.821 C32.2@53.125,82.927
  Top Layer w0.2: v1(38.8,121.25) v1(39.475,121.25) v1(40.15,121.25)
  Top Layer w0.21: C29.2@43.225,83.877 43.462,83.64 43.462,83.34 43.675,83.127 45.664,83.127 46.3,82.491 U26.39@46.3,81.797 ; 43.975,78.427 U26.50@44.53,78.427 ; 43.975,78.827 U26.49@44.53,78.827 ; U26.38@46.7,81.797 46.7,82.352 ; 47.1,73.677 U26.6@47.1,75.457 ; U26.11@49.1,75.457 49.1,74.67 49.74,74.03 49.74,73.802 ; U26.15@50.87,76.027 U26.15@50.945,76.027 U26.15@50.985,76.027 ; U26.20@50.87,78.027 51.425,78.027 ; U26.24@50.87,79.627 51.425,79.627 ; U26.25@50.87,80.027 52,80.027
  Top Layer w0.25: C56.2@40.3,74.577 41.075,74.577 42.15,75.652 42.15,77.496 43.081,78.427 43.975,78.427 ; C45.2@41.375,78.102 42.191,78.102 42.916,78.827 43.975,78.827 ; C30.2@46.125,83.902 46.194,83.833 46.194,83.135 46.7,82.629 46.7,82.352 ; 51.095,75.922 51.095,75.774 51.571,75.299 52.053,75.299 52.325,75.027 52.325,73.586 52.834,73.077 53.079,73.077 53.225,72.931 C67.2@53.225,72.377 ; 51.425,78.027 51.988,78.027 52.163,77.852 53.047,77.852 53.172,77.727 53.25,77.727 53.447,77.53 C46.2@53.447,77.452 ; 51.425,79.627 52.45,79.627 52.775,79.952
  Top Layer w0.3: R210.2@17.25,19.7 17.25,20.765 17.725,21.24 JP4.2@19.725,21.24 ; U23.3@21.494,101.121 21.494,102.956 v1(22.169,102.956) ; U31.3@29.695,55.275 31.53,55.275 v1@31.53,54.6 ; v1(35.25,16.88) R216.2@35.25,17.525 ; v1(39.475,121.25) R5.2@39.475,122.125 ; v3(46.765,72.937) 47.375,72.937 47.374,72.938 47.374,73.403 47.1,73.677 ; C68.2@49.55,72.207 C68.2@49.575,72.207 ; 49.74,73.802 49.74,73.096 49.575,72.931 C68.2@49.575,72.207 ; v3(50.16,72.207) C68.2@49.575,72.207 ; C67.2@53.225,72.377 v3(53.835,72.377) ; R18.1@128.023,113.05 v1(128.673,113.05) ; C162.2@151.045,12.85 151.045,11.28 v1(151.125,11.2) ; v1(161.7,65.1) C62.2@161.7,65.775 162.55,65.775 164.055,64.27 CN5.2@165.455,64.27
  Top Layer w0.4: v1(44.45,67.075) R56.1@44.45,67.802
  Top Layer w0.5: v1(29.45,37.925) D2.1@29.83,37.925 D2.1@30.225,37.925
  Top Layer w0.55: v1(122.025,24.125) v1(122.725,24.125) v1(122.725,24.825) v1(122.025,24.825) ; v1(151.125,11.2) v1(151.125,10.5) v1(151.125,9.8) v1(151.125,9.1) v1(151.125,8.4) Q5.5@152.615,8.4
  Top Layer w0.6: 52.775,79.952 53.1,80.277 C38.2@53.1,81.002
  Top Layer w0.8: C42.1@27.25,78.7 27.275,78.675 v1(28.525,78.675) ; v1(147.025,21.575) C147.1@148.275,21.575
  Top Layer w1: C143.2@122.375,23.25 L12.1@125.575,23.25
  Bottom Layer w0.4: R289.1@31.05,47.813 30.409,47.813 30.175,48.047 30.175,49.875 31.95,51.65 31.95,54.07 v1(31.475,54.545)
  other v3: 39.55,74.227 39.55,74.727 53.275,76.702 53.775,76.702 40.625,77.852 40.625,78.352 52.85,81.752 53.35,81.752 52.875,83.577 53.375,83.577 42.475,83.627 42.475,84.127 45.875,84.652 46.375,84.652
100MCLK0_N: R88.1 U33.10 | length 3
  Top Layer w0.09: R88.1@105.625,48.94 105.415,48.73 105.278,48.73 105.225,48.678 105.225,48.34 105.45,48.115 106.104,48.115 106.55,47.669 106.55,47.24 U33.10@106.625,47.165
100MCLK0_P: R87.1 U33.11 | length 3.2
  Top Layer w0.09: R87.1@104.575,48.94 104.785,48.73 104.922,48.73 104.975,48.678 104.975,48.237 105.073,48.138 105.346,47.865 106,47.865 106.15,47.715 106.3,47.565 106.3,47.24 106.175,47.115 U33.11@106.175,46.99
100MCLK1_N: R89.1 U33.9 | length 3.1
  Top Layer w0.09: U33.9@107.225,47.165 107.3,47.24 107.3,47.323 107.3,47.719 107.671,48.09 108.5,48.09 108.625,48.215 108.625,48.678 108.572,48.73 108.435,48.73 R89.1@108.225,48.94
100MCLK1_P: R90.1 U33.8 | length 3.3
  Top Layer w0.09: U33.8@107.675,46.99 107.675,47.115 107.55,47.24 107.55,47.426 107.55,47.615 107.775,47.84 108.604,47.84 108.875,48.112 108.875,48.678 108.928,48.73 109.065,48.73 R90.1@109.275,48.94
BOOT0: SW1.8 U27.R4 | length 72.7
  Top Layer w0.09: 84.655,69.035 85.264,69.035 85.354,69.125 87.525,69.125 U27.R4@88,69.6
  Top Layer w0.1: v1(65.75,69.275) 66.325,68.7 68.864,68.7 69.389,68.175 72.825,68.175 74.95,66.05 74.95,64.8 75.275,64.475 78.733,64.475 81.275,67.017 82.36,67.017 84.378,69.035 84.655,69.035
  Bottom Layer w0.1: SW1.8@54.885,108.625 66,97.51 66,90.375 67.9,88.475 67.9,84.508 66.475,83.083 66.475,70.717 65.75,69.992 v1(65.75,69.275)
BOOT1: SW1.7 U27.R3 | length 67.9
  Top Layer w0.09: 83.448,70.265 85.615,70.265 85.985,69.895 86.522,69.895 86.817,69.6 U27.R3@87.2,69.6
  Top Layer w0.1: v1(64.725,69.25) 65.675,70.2 81.974,70.2 82.099,70.325 83.388,70.325 83.448,70.265
  Bottom Layer w0.1: SW1.7@54.885,106.125 57.102,106.125 65.8,97.427 65.8,90.292 67.7,88.392 67.7,84.591 66.275,83.166 66.275,70.8 v1(64.725,69.25)
BOOT2: SW1.6 U27.T2 | length 71.1
  Top Layer w0.09: 84.65,68.41 85.613,68.41 86.003,68.8 U27.T2@86.4,68.8
  Top Layer w0.1: v1(65.75,67.917) 66.133,68.3 68.699,68.3 69.224,67.775 72.659,67.775 74.55,65.884 74.55,64.634 75.109,64.075 78.899,64.075 81.39,66.566 82.447,66.566 84.29,68.41 84.65,68.41
  Bottom Layer w0.1: SW1.6@54.885,103.625 59.319,103.625 65.6,97.344 65.6,90.209 67.5,88.309 67.5,84.674 66.075,83.249 66.075,71.417 64.275,69.617 64.275,68.725 64.525,68.475 65.192,68.475 v1(65.75,67.917)
BOOT3: SW1.5 U27.T1 | length 70
  Top Layer w0.1: v1(64.725,67.917) 65.308,68.5 68.781,68.5 69.306,67.975 72.742,67.975 74.75,65.967 74.75,64.717 75.192,64.275 78.816,64.275 81.308,66.766 82.378,66.766 84.412,68.8 U27.T1@85.6,68.8
  Bottom Layer w0.1: SW1.5@54.885,101.125 61.536,101.125 65.4,97.261 65.4,90.126 67.3,88.226 67.3,84.756 65.875,83.331 65.875,75.4 65.06,74.585 65.06,74.103 65.875,73.288 65.875,71.5 64.075,69.7 64.075,68.567 v1(64.725,67.917)
BUTTON.TAMP: B3.1 B3.2 C13.2 CN6.2 R30.1 U21.1 U27.M6 | length 147.3
  Top Layer w0.1: v2(89.2,71.6) U27.M6@89.6,72
  Top Layer w0.2: CN6.2@5.543,106.95 4,106.95 3.775,106.725 v1(2.812,106.725) C13.2@2.812,107.375 U21.1@2.812,108.563 B3.2@2.812,110.3 B3.1@10.763,110.3 B3.1@10.813,110.25
  Top Layer w0.4: R30.1@10.813,108.512 B3.1@10.813,110.25
  Signal Layer 2 w0.1: v2(2.812,70.938) 2.825,70.925 13.825,70.925 16.35,73.45 42.4,73.45 44.5,75.55 53.35,75.55 55.025,73.875 59.625,73.875 60.8,72.7 65.958,72.7 66.675,73.417 66.675,74.125 68.25,75.7 70.55,78 80.416,78 80.445,77.971 81.172,77.243 86.816,71.6 v2(89.2,71.6)
  Bottom Layer w0.1: v2(2.812,70.938) v1(2.812,106.725)
BUTTON.USER1: C12.2 R29.1 U27.E14 | length 94.8
  Top Layer w0.09: 95.675,83.725 95.675,82.25 95.945,81.98 95.945,80.457 96.05,80.352 96.05,79.588 96.31,79.328 96.31,77.91 U27.E14@96,77.6
  Top Layer w0.1: v1(28.825,95.075) 56.275,95.075 56.87,94.48 67.905,94.48 v1(68.25,94.825) ; v1(95.275,93.85) 95.275,84.125 95.675,83.725
  Top Layer w0.2: v1(28.813,104.325) C12.2@28.813,104.975 R29.1@28.813,105.825
  Signal Layer 2 w0.1: v1(68.25,94.825) 68.595,94.48 90.176,94.48 90.806,93.85 v1(95.275,93.85)
  Bottom Layer w0.1: v1(28.813,104.325) 28.813,95.088 v1(28.825,95.075)
BUTTON.USER2: C11.2 R28.1 U27.L5 | length 112.4
  Top Layer w0.1: v2(88.4,72.4) U27.L5@88.8,72.8
  Top Layer w0.2: v1(15.813,104.325) C11.2@15.813,104.975 R28.1@15.813,105.825
  Signal Layer 2 w0.1: v2@15.825,73.65 42.317,73.65 44.417,75.75 53.075,75.75 53.433,75.75 55.108,74.075 59.708,74.075 60.883,72.9 65.875,72.9 66.475,73.5 66.475,74.208 70.467,78.2 80.781,78.2 86.182,72.799 88,72.799 v2(88.4,72.4)
  Bottom Layer w0.1: v2(15.812,73.65) v1(15.813,104.325)
CAM_ENABLE: CN4.18 U16.1 U27.G5 | length 64.3
  Top Layer w0.09: 81.172,76.702 85.898,76.702 86.105,76.495 88.305,76.495 U27.G5@88.8,76
  Top Layer w0.1: CN4.18@77.75,120.75 77.75,119.6 78.055,119.295 78.055,118.942 v1(78.06,118.937) U16.1@78.06,118.312 ; v1(79.3,77.15) 79.748,76.702 81.172,76.702
  Bottom Layer w0.1: v1(78.06,118.937) 77.75,119.247 77.75,119.677 77.46,119.967 77.46,119.974 76.934,120.5 73.566,120.5 73.125,120.059 73.125,119.705 72.85,119.43 72.85,117.25 79.3,110.8 v1(79.3,77.15)
CAM_RESET: CN4.17 U15.1 U27.L6 | length 67.6
  Top Layer w0.1: CN4.17@77.25,120.75 77.26,120.74 v1(77.26,118.937) U15.1@77.26,118.312 ; v2(89.2,72.4) U27.L6@89.6,72.8
  Bottom Layer w0.1: v1(77.26,118.937) 77.26,119.891 76.851,120.3 73.649,120.3 73.325,119.976 73.325,119.6 73.05,119.325 73.05,117.4 73.813,116.637 79.721,116.637 83.25,113.108 83.25,76.225 87.445,72.03 88.83,72.03 v2(89.2,72.4)
COMBOTX1_N: C98.1 U27.AB19 | length 5.3
  Top Layer w0.09: U27.AB19@100,64 99.96,64.04 99.96,64.219 99.904,64.275 99.756,64.275 99.7,64.219 99.7,63.8 99.775,63.725 100.025,63.475 100.025,61.9 100.548,61.378 100.799,61.126 100.799,60.5 100.799,60.251 100.895,60.155 100.895,60.13 101,60.025 C98.1@101.025,60.025
COMBOTX1_P: C97.1 U27.AA19 | length 5.7
  Top Layer w0.09: U27.AA19@100,64.8 99.96,64.76 99.96,64.581 99.904,64.525 99.622,64.525 99.45,64.354 99.45,63.696 99.775,63.371 99.775,61.796 100.361,61.211 100.549,61.022 100.549,60.249 100.455,60.155 100.455,60.13 100.35,60.025 C97.1@100.325,60.025
CSI.CK_N: U17.9 U27.D6 | length 47.3
  Top Layer w0.09: U17.9@69.775,116.725 69.83,116.67 69.83,116.387 69.85,116.367 69.85,116.046 69.996,115.9 83.675,102.221 83.675,84.963 86.488,82.15 87.826,82.15 88.715,81.261 88.715,80.495 89.085,80.125 89.085,78.915 U27.D6@89.6,78.4
CSI.CK_P: U17.10 U27.C6 | length 47
  Top Layer w0.09: U17.10@70.175,116.725 70.12,116.67 70.12,116.387 70.1,116.367 70.1,116.15 83.925,102.325 83.925,85.066 86.591,82.4 87.93,82.4 88.965,81.365 88.965,80.599 89.335,80.229 89.335,79.053 89.473,78.915 89.547,78.915 89.6,78.968 U27.C6@89.6,79.2
CSI.CKcon_N: CN4.8 U17.2 | length 9.6
  Top Layer w0.09: v1(69.6,118.75) 69.6,118.745 69.85,118.495 69.85,118.133 69.83,118.113 69.83,117.83 U17.2@69.775,117.775 ; v1(72.625,122.363) 72.875,122.113 72.875,121.348 72.855,121.328 72.855,121.295 72.75,121.19 CN4.8@72.75,120.75 ; v1@72.625,122.413 v1@72.65,122.388
  Bottom Layer w0.09: v1(69.6,118.75) 69.6,118.755 69.85,119.005 69.85,120.529 70.121,120.8 72.75,120.8 72.875,120.925 72.875,122.113 v1(72.625,122.363) ; v1@72.625,122.413 v1@72.65,122.388
CSI.CKcon_P: CN4.9 U17.1 | length 9.6
  Top Layer w0.09: U17.1@70.175,117.775 70.12,117.83 70.12,118.113 70.1,118.133 70.1,118.495 70.35,118.745 v1(70.35,118.75) ; CN4.9@73.25,120.75 73.145,120.855 73.145,121.328 73.125,121.348 73.125,122.163 v1(73.375,122.413)
  Bottom Layer w0.09: v1(70.35,118.75) 70.35,118.755 70.1,119.005 70.1,120.425 70.225,120.55 72.854,120.55 73.125,120.821 73.125,122.163 v1(73.375,122.413)
CSI.D0_N: U17.7 U27.B5 | length 46.7
  Top Layer w0.09: U17.7@68.975,116.725 68.92,116.67 68.92,116.387 68.9,116.367 68.9,116.293 68.9,115.325 69.177,115.048 76.016,108.209 81.484,102.741 83.025,101.2 83.025,84.8 86.075,81.75 87.9,81.75 88.535,81.115 88.535,81.011 88.535,79.853 88.673,79.715 88.747,79.715 88.8,79.768 U27.B5@88.8,80
CSI.D0_P: U17.6 U27.C5 | length 47
  Top Layer w0.09: U17.6@68.575,116.725 68.63,116.67 68.63,116.387 68.65,116.367 68.65,116.189 68.65,115.221 75.839,108.033 81.308,102.564 82.775,101.096 82.775,84.696 83.173,84.298 85.971,81.5 87.796,81.5 88.106,81.19 88.285,81.011 88.285,79.715 U27.C5@88.8,79.2
CSI.D0con_N: CN4.2 U17.4 | length 9.5
  Top Layer w0.09: v1@68.325,119.8 68.075,119.55 68.075,119.304 68.9,118.479 68.9,118.133 68.92,118.113 68.92,117.83 U17.4@68.975,117.775 ; v1(69.625,122.403) 69.875,122.153 69.875,121.348 69.855,121.328 69.855,121.295 69.75,121.19 CN4.2@69.75,120.79 ; v1@69.625,122.453 v1@69.65,122.428
  Bottom Layer w0.09: v1(68.325,119.805) 68.325,119.811 68.075,120.061 68.075,121.975 69.121,123.021 69.8,123.021 69.875,122.946 69.875,122.658 69.625,122.408 v1(69.625,122.403)
CSI.D0con_P: CN4.3 U17.5 | length 10.3
  Top Layer w0.09: v1@67.575,119.8 67.825,119.55 67.825,119.2 67.95,119.075 68.65,118.375 68.65,118.133 68.63,118.113 68.63,117.83 U17.5@68.575,117.775 ; CN4.3@70.25,120.79 70.25,121.19 70.145,121.295 70.145,121.328 70.125,121.348 70.125,122.203 v1(70.375,122.453)
  Bottom Layer w0.09: v1(67.575,119.805) 67.575,119.811 67.825,120.061 67.825,122.079 69.018,123.271 69.904,123.271 70.125,123.05 70.125,122.708 70.375,122.458 v1(70.375,122.453)
CSI.D1_N: U18.5 U27.E7 | length 47.3
  Top Layer w0.09: U18.5@71.85,116.725 71.905,116.67 71.905,116.387 71.925,116.367 71.925,116.293 71.925,115.321 72.097,115.149 81.853,105.394 83.719,103.527 84.6,102.646 84.6,85.121 86.771,82.95 87.634,82.95 89.145,81.439 89.145,80.673 89.52,80.298 89.52,79.693 89.885,79.328 89.885,78.115 U27.E7@90.4,77.6
CSI.D1_P: U18.6 U27.D7 | length 47
  Top Layer w0.09: U18.6@72.25,116.725 72.195,116.67 72.195,116.387 72.175,116.367 72.175,116.189 72.175,115.425 82.03,105.57 83.896,103.704 84.85,102.75 84.85,85.225 86.875,83.2 87.738,83.2 89.395,81.543 89.395,81.439 89.395,80.91 89.394,80.909 89.394,80.776 89.75,80.42 89.75,79.788 90.115,79.424 90.115,78.273 90.273,78.115 90.347,78.115 90.4,78.168 U27.D7@90.4,78.4
CSI.D1con_N: CN4.5 U18.2 | length 12.6
  Top Layer w0.09: CN4.5@71.25,120.75 71.25,120.205 71.375,120.08 71.375,119.215 71.59,119 73.2,119 73.35,118.85 73.35,116.671 74.075,115.946 74.075,115.85 73.875,115.65 73.525,115.65 72.95,116.225 72.95,118.379 72.604,118.725 72.146,118.725 71.925,118.504 71.925,118.133 71.905,118.113 71.905,117.83 U18.2@71.85,117.775
CSI.D1con_P: CN4.6 U18.1 | length 12.6
  Top Layer w0.09: CN4.6@71.75,120.75 71.75,120.205 71.625,120.08 71.625,119.319 71.694,119.25 73.304,119.25 73.426,119.127 73.6,118.954 73.6,116.775 74.325,116.05 74.325,115.746 73.979,115.4 73.421,115.4 72.7,116.121 72.7,118.275 72.575,118.4 72.5,118.475 72.25,118.475 72.175,118.4 72.175,118.133 72.195,118.113 72.195,117.83 U18.1@72.25,117.775
DDR_A0: R265.1 U27.K18 U28.P3 U29.P3 | length 57.4
  Top Layer w0.09: U27.K18@99.2,73.6 v2(99.6,74) ; v4(111.9,66.825) 111.941,66.825 112.294,66.472 U29.P3@112.294,66.422 ; v4@129.532,73.928 129.572,73.928 129.925,73.575 U28.P3@129.925,73.55 U28.P3@129.925,73.525
  Bottom Layer w0.09: v2(99.6,74) 100.267,73.333 100.646,73.333 100.771,73.209 102.988,73.209 103.252,72.945 106.961,72.945 108.091,71.815 108.091,71.615 107.965,71.49 106.3,71.49 106.077,71.267 106.077,70.58 106.3,70.357 109.549,70.357 110.095,69.811 110.095,69.06 109.909,68.874 109.909,68.291 110.177,68.022 111.269,68.022 111.5,67.791 111.5,67.301 111.894,66.908 112.38,66.422 112.983,66.422 114.772,64.633 117.533,64.633 117.9,65 119.375,65 119.575,65.2 119.575,65.459 120.513,66.397 120.513,66.588 120.885,66.96 120.885,67.391 121.7,68.206 121.7,68.718 121.76,68.779 121.76,69.109 122.92,70.269 122.92,70.774 122.921,70.775 122.921,70.812 127.443,75.333 128.702,75.333 129.12,74.915 129.12,74.596 129.362,74.355 129.434,74.355 129.511,74.278 129.511,74.109 129.454,74.052 129.525,73.981 129.525,73.975 129.551,73.95 130.09,73.95 130.245,73.795 130.363,73.795 132.433,71.725 136.35,71.725 136.825,72.2 R265.1@137.5,72.2
  other v4: 129.525,73.95
DDR_A1: R281.1 U27.P16 U28.P7 U29.P7 | length 54.7
  Top Layer w0.09: U27.P16@97.6,70.4 v2(97.975,70.025) ; v4(111.9,62.825) U29.P7@112.3,63.225 ; v4@129.54,69.936 U28.P7@129.932,70.328
  Bottom Layer w0.09: v2(97.975,70.025) 97.975,69.95 98.25,69.675 99.45,69.675 99.53,69.595 99.693,69.595 100.029,69.259 101.146,69.259 101.995,68.41 101.995,66.636 102.285,66.347 103.212,66.347 106.181,63.378 106.972,63.378 107.099,63.25 107.099,61.878 107.235,61.742 108.219,61.742 108.555,62.078 108.555,62.657 108.702,62.804 109.281,62.804 109.834,63.357 110.575,63.357 110.675,63.457 111.319,63.457 111.37,63.405 111.9,62.875 v4(111.9,62.825) ; v4@111.9,62.816 111.9,62.504 111.985,62.42 112.064,62.42 112.295,62.189 112.295,61.694 112.365,61.624 112.365,60.958 113.803,59.52 121.655,59.52 124.605,62.47 124.605,64.183 126.361,65.939 126.361,69.387 127.456,70.482 128.43,70.482 128.483,70.535 129.004,70.535 129.525,70.014 v4(129.525,69.95) 129.525,69.9 129.725,69.7 129.725,69.509 129.92,69.314 129.92,68.88 130.035,68.765 130.035,67.886 130.722,67.2 131.225,67.2 131.9,66.525 R281.1@131.975,66.525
